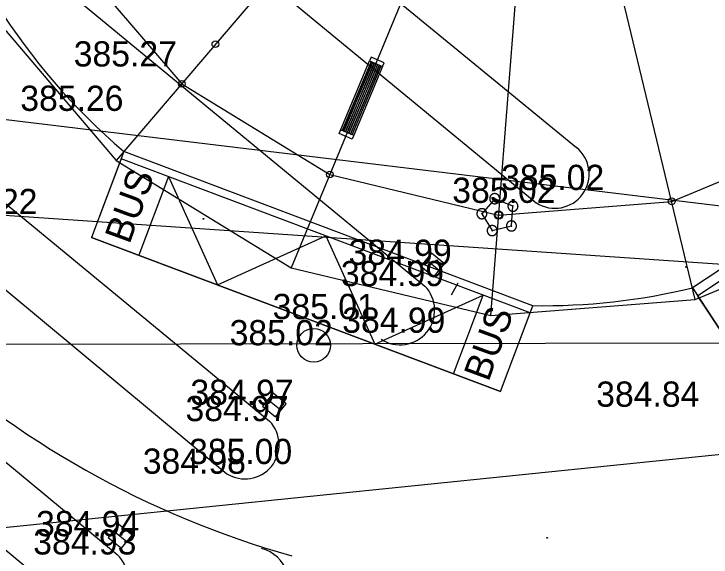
# Model space of a CAD drawing. Extents: x -438233 to -437334, y -1133133 to -1132623.
# Drawn here: x -438073.66 to -438052.93, y -1132978.53 to -1132962.38 of the extents above; entities that cross this region are included whole.
import ezdxf

# ---------------------------------------------------------------- set-up
doc = ezdxf.new("R2010")
doc.units = 0
for name, color, linetype in [('MOBILIÁŘ', 7, 'Continuous'), ('OSY', 7, 'Continuous'), ('SILNA 1', 7, 'Continuous'), ('SILNA 2', 7, 'Continuous'), ('TENKA', 7, 'Continuous'), ('urban islands', 7, 'Continuous'), ('Vrstva 1', 7, 'Continuous'), ('Vrstva 10', 7, 'Continuous'), ('Vrstva 27', 7, 'Continuous'), ('Vrstva 3', 7, 'Continuous'), ('Vrstva 40', 7, 'Continuous')]:
    doc.layers.add(name, color=color, linetype=linetype)

# ---------------------------------------------------------------- blocks, each defined once
blk = doc.blocks.new('A$C32EE4163')
at = {"layer": 'SILNA 1'}
for radius in [1.25, 1.25, 1.13, 1.13]:
    blk.add_circle((0, 0), radius, dxfattribs=at)
blk = doc.blocks.new('A$C1C6D51B8')
at = {"layer": 'urban islands'}
for p, q in [((-23400, 4190), (-1200, 4190)), ((-1200, 3710), (-23400, 3710)), ((-23400, 3660), (-1200, 3660)), ((-23400, 3239), (-23400, 3300)), ((-23400, 3180), (-1200, 3180)), ((-22900, 3710), (-22900, 3660)), ((-22900, 3180), (-22900, 3130)), ((-22900, 2650), (-22900, 2600)), ((-22900, 2120), (-22900, 2070)), ((-22290, 3660), (-22290, 3710)), ((-22290, 3130), (-22290, 3180)), ((-21900, 3180), (-21900, 3130)), ((-21900, 2650), (-21900, 2600)), ((-21900, 2120), (-21900, 2070)), ((-19450, 3710), (-19450, 3660)), ((-19450, 3180), (-19450, 3130)), ((-19450, 2650), (-19450, 2600)), ((-19450, 2120), (-19450, 2070)), ((-18950, 3660), (-18950, 3710)), ((-18950, 3180), (-18950, 3130)), ((-18950, 2650), (-18950, 2600)), ((-18950, 2120), (-18950, 2070)), ((-14850, 3710), (-14850, 3660)), ((-14850, 3180), (-14850, 3130)), ((-14850, 2650), (-14850, 2600)), ((-14850, 2120), (-14850, 2070)), ((-14350, 3660), (-14350, 3710)), ((-14350, 3180), (-14350, 3130)), ((-14350, 2650), (-14350, 2600)), ((-14350, 2120), (-14350, 2070)), ((-10250, 3710), (-10250, 3660)), ((-10250, 3180), (-10250, 3130)), ((-10250, 2650), (-10250, 2600)), ((-10250, 2120), (-10250, 2070)), ((-9750, 3660), (-9750, 3710)), ((-9750, 3180), (-9750, 3130)), ((-9750, 2650), (-9750, 2600)), ((-9750, 2120), (-9750, 2070)), ((-5650, 3710), (-5650, 3660)), ((-5650, 3180), (-5650, 3130)), ((-5650, 2650), (-5650, 2600)), ((-5650, 2120), (-5650, 2070)), ((-5150, 3660), (-5150, 3710)), ((-5150, 3180), (-5150, 3130)), ((-5150, 2650), (-5150, 2600)), ((-5150, 2120), (-5150, 2070)), ((-2700, 3130), (-2700, 3180)), ((-2700, 2600), (-2700, 2650)), ((-2700, 2070), (-2700, 2120)), ((-2310, 3710), (-2310, 3660)), ((-2310, 3180), (-2310, 3130)), ((-2300, 3710), (-2300, 3660)), ((-1700, 3710), (-1700, 3660)), ((-1700, 3180), (-1700, 3130)), ((-1700, 2650), (-1700, 2600)), ((-1700, 2120), (-1700, 2070)), ((-1200, 3214), (-1200, 3200)), ((-23400, 976), (-23400, 978)), ((-23400, 815), (-23400, 911)), ((-23400, 530), (-1200, 530)), ((-23400, 480), (-1200, 480)), ((-22900, 1590), (-22900, 1540)), ((-22900, 1060), (-22900, 1010)), ((-22900, 480), (-22900, 530)), ((-22290, 1010), (-22290, 1060)), ((-22290, 530), (-22290, 480)), ((-21900, 1590), (-21900, 1540)), ((-21900, 1060), (-21900, 1010)), ((-19450, 1590), (-19450, 1540)), ((-19450, 1060), (-19450, 1010)), ((-19450, 530), (-19450, 480)), ((-18950, 1590), (-18950, 1540)), ((-18950, 1060), (-18950, 1010)), ((-18950, 480), (-18950, 530)), ((-14850, 1590), (-14850, 1540)), ((-14850, 1060), (-14850, 1010)), ((-14850, 530), (-14850, 480)), ((-14350, 1590), (-14350, 1540)), ((-14350, 1060), (-14350, 1010)), ((-14350, 480), (-14350, 530)), ((-10250, 1590), (-10250, 1540)), ((-10250, 1060), (-10250, 1010)), ((-10250, 530), (-10250, 480)), ((-9750, 1590), (-9750, 1540)), ((-9750, 1060), (-9750, 1010)), ((-9750, 480), (-9750, 530)), ((-5650, 1590), (-5650, 1540)), ((-5650, 1060), (-5650, 1010)), ((-5650, 530), (-5650, 480)), ((-5150, 1590), (-5150, 1540)), ((-5150, 1060), (-5150, 1010)), ((-5150, 480), (-5150, 530)), ((-2700, 1540), (-2700, 1590)), ((-2700, 1010), (-2700, 1060)), ((-2310, 1060), (-2310, 1010)), ((-2310, 480), (-2310, 530)), ((-2300, 530), (-2300, 480)), ((-1700, 1590), (-1700, 1540)), ((-1700, 1060), (-1700, 1010)), ((-1700, 530), (-1700, 480)), ((-1200, 890), (-1200, 951))]:
    blk.add_line(p, q, dxfattribs=at)
for points in [[(-1200, 0), (-1200, 4190), (0, 4190), (0, 0), (-23400, 0), (-23400, 4190), (-24600, 4190), (-24600, 0), (-23400, 0)], [(-23400, 3130), (-1200, 3130), (-1200, 2650), (-23400, 2650)], [(-2505, 3165), (-2531, 3180)], [(-2479, 3180), (-2505, 3165)], [(-1200, 3375), (-1200, 3279), (-1200, 3440)], [(-1200, 3241), (-1200, 3180), (-1200, 3241)], [(-1200, 1060), (-23400, 1060), (-23400, 1540), (-1200, 1540)], [(-23400, 949), (-23400, 1010), (-1200, 1010)], [(-2531, 1010), (-2505, 1025)], [(-2505, 1025), (-2479, 1010)]]:
    blk.add_lwpolyline(points, dxfattribs=at)
for points in [[(-1200, 2120), (-23400, 2120), (-23400, 2600), (-1200, 2600)], [(-23400, 2070), (-1200, 2070), (-1200, 1590), (-23400, 1590)]]:
    blk.add_lwpolyline(points, close=True, dxfattribs=at)
for centre, radius, start, end in [((-2505, 3240), 80, 228.59038, 311.40962), ((-2505, 3243), 67.7, 247.84515, 292.15485), ((-2505, 950), 80, 48.59038, 131.40962), ((-2505, 947), 67.7, 67.84515, 112.15485)]:
    blk.add_arc(centre, radius, start, end, dxfattribs=at)
blk = doc.blocks.new('A$C7A6F5A01')
at = {"layer": 'Vrstva 1'}
for p, q in [((-20, 32), (-39, 0)), ((-39, 0), (-20, -35)), ((18, 32), (-20, 32)), ((40, 0), (18, 32)), ((18, -35), (40, 0)), ((-20, -35), (18, -35))]:
    blk.add_line(p, q, dxfattribs=at)
for points in [[(1497, 0), (1491, 133), (1481, 203), (1479, 219), (1476, 236), (1474, 253), (1471, 269), (1468, 286), (1465, 302), (1461, 319), (1458, 335), (1454, 351), (1450, 367), (1446, 383), (1442, 399), (1437, 415), (1432, 431), (1428, 447), (1423, 463), (1418, 478), (1412, 494), (1407, 509), (1401, 524), (1396, 540), (1390, 555), (1383, 570), (1377, 585), (1371, 600), (1364, 615), (1358, 630), (1351, 644), (1344, 659), (1336, 673), (1329, 688), (1322, 702), (1314, 716), (1306, 730), (1298, 744), (1290, 758), (1282, 772), (1274, 786), (1265, 799), (1256, 813), (1248, 826), (1239, 840), (1229, 853), (1220, 866), (1211, 879), (1201, 892), (1192, 905), (1182, 917), (1172, 930), (1162, 942), (1152, 955), (1142, 967), (1131, 979), (1121, 991), (1110, 1003), (1099, 1015), (1088, 1026), (1077, 1038), (1066, 1049), (1055, 1061), (1044, 1072), (1032, 1083), (1020, 1094), (1009, 1105), (997, 1115), (985, 1126), (973, 1136), (961, 1147), (948, 1157), (936, 1167), (923, 1177), (911, 1186), (898, 1196), (885, 1206), (872, 1215), (859, 1224), (846, 1233), (833, 1242), (819, 1251), (806, 1260), (792, 1268), (779, 1277), (765, 1285), (751, 1293), (737, 1301), (723, 1309), (709, 1317), (695, 1324), (681, 1332), (666, 1339), (652, 1346), (637, 1353), (623, 1360), (608, 1366), (593, 1373), (578, 1379), (563, 1385), (548, 1391), (533, 1397), (518, 1403), (503, 1409), (487, 1414), (472, 1419), (456, 1424), (441, 1429), (425, 1434), (409, 1438), (394, 1443), (378, 1447), (362, 1451), (346, 1455), (330, 1459), (314, 1462), (298, 1466), (281, 1469), (265, 1472), (249, 1475), (232, 1478), (216, 1480), (200, 1482), (183, 1485), (166, 1487), (150, 1488), (133, 1490), (116, 1491), (99, 1493), (83, 1494), (66, 1495), (-67, 1495), (-85, 1494), (-102, 1493), (-120, 1491), (-137, 1490), (-154, 1488), (-172, 1486), (-189, 1484), (-206, 1482), (-223, 1479), (-240, 1477), (-257, 1474), (-274, 1471), (-290, 1467), (-307, 1464), (-324, 1460), (-341, 1457), (-357, 1453), (-374, 1448), (-390, 1444), (-406, 1440), (-422, 1435), (-439, 1430), (-455, 1425), (-471, 1420), (-487, 1414), (-503, 1409), (-518, 1403), (-534, 1397), (-550, 1391), (-565, 1385), (-581, 1378), (-596, 1372), (-611, 1365), (-626, 1358), (-642, 1351), (-657, 1344), (-671, 1336), (-686, 1329), (-701, 1321), (-716, 1313), (-730, 1305), (-744, 1297), (-759, 1289), (-773, 1280), (-787, 1272), (-801, 1263), (-815, 1254), (-829, 1245), (-843, 1236), (-856, 1226), (-870, 1217), (-883, 1207), (-896, 1197), (-909, 1187), (-922, 1177), (-935, 1167), (-948, 1156), (-961, 1146), (-973, 1135), (-986, 1124), (-998, 1114), (-1010, 1102), (-1023, 1091), (-1035, 1080), (-1046, 1069), (-1058, 1057), (-1070, 1045), (-1081, 1033), (-1092, 1021), (-1104, 1009), (-1115, 997), (-1126, 985), (-1136, 972), (-1147, 960), (-1158, 947), (-1168, 934), (-1178, 921), (-1188, 908), (-1198, 895), (-1208, 882), (-1218, 869), (-1227, 855), (-1237, 841), (-1246, 828), (-1255, 814), (-1264, 800), (-1273, 786), (-1281, 772), (-1290, 758), (-1298, 743), (-1306, 729), (-1314, 714), (-1322, 700), (-1330, 685), (-1338, 670), (-1345, 655), (-1352, 640), (-1359, 625), (-1366, 610), (-1373, 594), (-1379, 579), (-1386, 564), (-1392, 548), (-1398, 532), (-1404, 517), (-1410, 501), (-1415, 485), (-1420, 469), (-1426, 453), (-1431, 437), (-1435, 420), (-1440, 404), (-1445, 388), (-1449, 371), (-1453, 355), (-1457, 338), (-1461, 321), (-1464, 304), (-1467, 288), (-1471, 271), (-1474, 254), (-1476, 237), (-1479, 220), (-1481, 202), (-1484, 185), (-1486, 168), (-1487, 150), (-1489, 133), (-1495, 67), (-1495, -66), (-1489, -136), (-1488, -153), (-1486, -170), (-1484, -186), (-1482, -203), (-1479, -220), (-1477, -236), (-1474, -253), (-1472, -269), (-1469, -285), (-1465, -302), (-1462, -318), (-1458, -334), (-1455, -350), (-1451, -366), (-1447, -382), (-1442, -398), (-1438, -414), (-1433, -429), (-1429, -445), (-1424, -461), (-1419, -476), (-1413, -492), (-1408, -507), (-1402, -522), (-1397, -537), (-1391, -552), (-1385, -568), (-1378, -582), (-1372, -597), (-1366, -612), (-1359, -627), (-1352, -641), (-1345, -656), (-1338, -670), (-1330, -685), (-1323, -699), (-1315, -713), (-1308, -727), (-1300, -741), (-1292, -755), (-1283, -769), (-1275, -783), (-1267, -796), (-1258, -810), (-1249, -823), (-1240, -837), (-1231, -850), (-1222, -863), (-1213, -876), (-1203, -889), (-1193, -902), (-1184, -914), (-1174, -927), (-1164, -939), (-1154, -952), (-1143, -964), (-1133, -976), (-1122, -988), (-1112, -1000), (-1101, -1012), (-1090, -1024), (-1079, -1035), (-1068, -1047), (-1057, -1058), (-1045, -1069), (-1034, -1080), (-1022, -1091), (-1010, -1102), (-999, -1113), (-987, -1124), (-974, -1134), (-962, -1145), (-950, -1155), (-938, -1165), (-925, -1175), (-912, -1185), (-900, -1194), (-887, -1204), (-874, -1213), (-861, -1223), (-848, -1232), (-834, -1241), (-821, -1250), (-808, -1259), (-794, -1267), (-780, -1276), (-767, -1284), (-753, -1292), (-739, -1300), (-725, -1308), (-711, -1316), (-696, -1324), (-682, -1331), (-668, -1338), (-653, -1346), (-639, -1353), (-624, -1360), (-609, -1366), (-595, -1373), (-580, -1379), (-565, -1385), (-550, -1392), (-534, -1397), (-519, -1403), (-504, -1409), (-489, -1414), (-473, -1420), (-458, -1425), (-442, -1430), (-426, -1434), (-411, -1439), (-395, -1444), (-379, -1448), (-363, -1452), (-347, -1456), (-331, -1460), (-315, -1463), (-299, -1467), (-283, -1470), (-266, -1473), (-250, -1476), (-233, -1479), (-217, -1481), (-200, -1484), (-184, -1486), (-167, -1488), (-151, -1490), (-134, -1491), (-67, -1495), (-1, -1495), (17, -1495), (34, -1494), (51, -1494), (68, -1494), (85, -1493), (103, -1492), (120, -1491), (137, -1489), (154, -1488), (171, -1486), (188, -1484), (204, -1482), (221, -1480), (238, -1477), (255, -1474), (271, -1471), (288, -1468), (305, -1465), (321, -1461), (338, -1458), (354, -1454), (370, -1450), (387, -1446), (403, -1441), (419, -1436), (435, -1432), (451, -1427), (467, -1422), (483, -1416), (498, -1411), (514, -1405), (530, -1399), (545, -1393), (561, -1387), (576, -1381), (592, -1374), (607, -1367), (622, -1361), (637, -1354), (652, -1346), (667, -1339), (682, -1331), (697, -1324), (711, -1316), (726, -1308), (740, -1300), (755, -1291), (769, -1283), (783, -1274), (797, -1265), (811, -1257), (825, -1247), (839, -1238), (852, -1229), (866, -1219), (879, -1210), (893, -1200), (906, -1190), (919, -1180), (932, -1169), (945, -1159), (958, -1149), (970, -1138), (983, -1127), (995, -1116), (1008, -1105), (1020, -1094), (1032, -1082), (1044, -1071), (1056, -1059), (1067, -1048), (1079, -1036), (1090, -1024), (1102, -1012), (1113, -999), (1124, -987), (1135, -975), (1146, -962), (1156, -949), (1167, -936), (1177, -923), (1187, -910), (1197, -897), (1207, -884), (1217, -870), (1227, -857), (1236, -843), (1246, -830), (1255, -816), (1264, -802), (1273, -788), (1281, -773), (1290, -759), (1298, -745), (1307, -730), (1315, -716), (1323, -701), (1330, -686), (1338, -671), (1346, -656), (1353, -641), (1360, -626), (1367, -611), (1374, -595), (1380, -580), (1387, -564), (1393, -549), (1399, -533), (1405, -517), (1410, -501), (1416, -486), (1421, -469), (1427, -453), (1431, -437), (1436, -421), (1441, -405), (1445, -388), (1450, -372), (1454, -355), (1457, -338), (1461, -322), (1465, -305), (1468, -288), (1471, -271), (1474, -254), (1476, -237), (1479, -220), (1481, -203), (1491, -136), (1494, -66)], [(-1, -101), (18, -98), (37, -92), (39, -91), (41, -90), (43, -89), (45, -88), (47, -87), (49, -86), (51, -85), (53, -84), (55, -83), (57, -82), (58, -81), (60, -80), (62, -78), (63, -77), (65, -76), (67, -75), (68, -73), (70, -72), (71, -70), (73, -69), (74, -68), (75, -66), (77, -65), (78, -63), (79, -62), (80, -60), (82, -59), (83, -57), (84, -55), (85, -54), (86, -52), (87, -50), (88, -49), (89, -47), (90, -45), (90, -44), (91, -42), (92, -40), (93, -38), (94, -37), (94, -35), (95, -33), (95, -31), (96, -29), (97, -28), (97, -26), (98, -24), (98, -22), (98, -20), (99, -18), (99, -16), (99, -15), (100, -13), (100, -11), (100, -9), (100, -7), (100, -5), (100, -3), (100, -1), (100, 1), (100, 2), (100, 4), (100, 6), (100, 8), (100, 10), (100, 12), (99, 14), (99, 16), (99, 18), (98, 19), (98, 21), (98, 23), (97, 25), (97, 27), (96, 29), (95, 31), (95, 32), (94, 34), (94, 36), (93, 38), (92, 40), (91, 41), (91, 43), (90, 45), (89, 47), (88, 48), (87, 50), (86, 52), (85, 53), (84, 55), (83, 57), (82, 58), (81, 60), (79, 61), (78, 63), (77, 64), (76, 66), (74, 67), (73, 69), (71, 70), (70, 72), (69, 73), (67, 74), (66, 76), (64, 77), (62, 78), (61, 79), (59, 81), (57, 82), (56, 83), (54, 84), (52, 85), (50, 86), (48, 87), (46, 88), (44, 89), (42, 90), (40, 91), (38, 92), (36, 93), (34, 94), (32, 94), (30, 95), (27, 96), (25, 96), (23, 97), (21, 98), (18, 98), (-17, 98), (-19, 98), (-21, 97), (-23, 96), (-26, 96), (-28, 95), (-30, 94), (-32, 94), (-34, 93), (-36, 92), (-38, 91), (-40, 90), (-42, 89), (-44, 88), (-46, 87), (-48, 86), (-50, 85), (-52, 84), (-54, 83), (-55, 82), (-57, 81), (-59, 80), (-60, 78), (-62, 77), (-64, 76), (-65, 75), (-67, 73), (-68, 72), (-70, 71), (-71, 69), (-72, 68), (-74, 66), (-75, 65), (-76, 63), (-78, 62), (-79, 60), (-80, 59), (-81, 57), (-82, 56), (-83, 54), (-85, 52), (-86, 51), (-87, 49), (-87, 47), (-88, 46), (-89, 44), (-90, 42), (-91, 41), (-92, 39), (-92, 37), (-93, 35), (-94, 34), (-94, 32), (-95, 30), (-96, 28), (-96, 26), (-97, 25), (-97, 23), (-98, 21), (-98, 19), (-98, 17), (-99, 15), (-99, 13), (-99, 12), (-99, 10), (-100, 8), (-100, 6), (-100, 4), (-100, 2), (-100, 0), (-100, -2), (-100, -3), (-100, -5), (-100, -7), (-100, -9), (-99, -11), (-99, -13), (-99, -15), (-99, -17), (-98, -18), (-98, -20), (-98, -22), (-97, -24), (-97, -26), (-96, -28), (-96, -29), (-95, -31), (-94, -33), (-94, -35), (-93, -37), (-92, -38), (-92, -40), (-91, -42), (-90, -44), (-89, -45), (-88, -47), (-87, -49), (-86, -50), (-85, -52), (-84, -54), (-83, -55), (-82, -57), (-80, -58), (-79, -60), (-78, -62), (-77, -63), (-75, -65), (-74, -66), (-72, -68), (-71, -69), (-70, -71), (-68, -72), (-66, -73), (-65, -75), (-63, -76), (-61, -77), (-60, -79), (-58, -80), (-56, -81), (-54, -82), (-52, -83), (-50, -85), (-48, -86), (-46, -87), (-44, -88), (-42, -89), (-40, -90), (-38, -91), (-36, -92), (-17, -98)]]:
    blk.add_lwpolyline(points, close=True, dxfattribs=at)
blk = doc.blocks.new('A$C5CBC2F6B')
at = {"layer": 'DEFPOINTS'}
blk.add_lwpolyline([(0, 5), (-4.76, 1.55), (-2.94, -4.05), (2.94, -4.05), (4.76, 1.55)], close=True, dxfattribs=at)
at = {"layer": 'MOBILIÁŘ', "xscale": 0.001, "yscale": 0.001}
for p in [(0, 5), (-4.75, 1.55), (4.76, 1.55), (-2.94, -4.05), (2.94, -4.05)]:
    blk.add_blockref('A$C7A6F5A01', p, dxfattribs=at)

msp = doc.modelspace()

# ---------------------------------------------------------------- linework, layer by layer
at = {"layer": 'OSY'}
for p, q in [((-438064.453, -1132959.52), (-438070.62, -1132966.746)), ((-438064.453, -1132959.52), (-438070.62, -1132966.746)), ((-438061.785, -1132961.153), (-438065.417, -1132969.932)), ((-438053.402, -1132970.872), (-438055.623, -1132961.636)), ((-438059.484, -1132971.354), (-438058.742, -1132961.883)), ((-438059.484, -1132971.354), (-438058.742, -1132961.883))]:
    msp.add_line(p, q, dxfattribs=at)
for points in [[(-438050.507, -1132933.894), (-438056.44, -1132932.473), (-438062.522, -1132932.954), (-438068.157, -1132935.291), (-438072.795, -1132939.255), (-438075.98, -1132944.458), (-438077.402, -1132950.391), (-438076.921, -1132956.473), (-438074.584, -1132962.109), (-438070.62, -1132966.746), (-438065.417, -1132969.932), (-438059.484, -1132971.354), (-438053.402, -1132970.872), (-438047.766, -1132968.535), (-438043.129, -1132964.571), (-438039.943, -1132959.368), (-438038.521, -1132953.435), (-438039.002, -1132947.353), (-438041.339, -1132941.718), (-438045.304, -1132937.08)], [(-438056.674, -1132935.463), (-438061.82, -1132935.87), (-438066.589, -1132937.848), (-438070.513, -1132941.202), (-438073.208, -1132945.605), (-438074.411, -1132950.625), (-438074.004, -1132955.771), (-438072.027, -1132960.54), (-438068.673, -1132964.464), (-438064.27, -1132967.16), (-438059.25, -1132968.363), (-438054.103, -1132967.956), (-438049.335, -1132965.978), (-438045.411, -1132962.624), (-438042.715, -1132958.221), (-438041.512, -1132953.201), (-438041.919, -1132948.055), (-438043.897, -1132943.286), (-438047.251, -1132939.362), (-438051.654, -1132936.666)], [(-438056.674, -1132935.463), (-438061.82, -1132935.87), (-438066.589, -1132937.848), (-438070.513, -1132941.202), (-438073.208, -1132945.605), (-438074.411, -1132950.625), (-438074.004, -1132955.771), (-438072.027, -1132960.54), (-438068.673, -1132964.464), (-438064.27, -1132967.16), (-438059.25, -1132968.363), (-438054.103, -1132967.956), (-438049.335, -1132965.978), (-438045.411, -1132962.624), (-438042.715, -1132958.221), (-438041.512, -1132953.201), (-438041.919, -1132948.055), (-438043.897, -1132943.286), (-438047.251, -1132939.362), (-438051.654, -1132936.666)]]:
    msp.add_lwpolyline(points, close=True, dxfattribs=at)
at = {"layer": 'SILNA 1'}
for centre in [(-438067.672, -1132963.284), (-438068.673, -1132964.464), (-438068.673, -1132964.464), (-438064.27, -1132967.16), (-438064.27, -1132967.16), (-438054.104, -1132967.956), (-438054.104, -1132967.956), (-438059.25, -1132968.363), (-438059.25, -1132968.363)]:
    msp.add_circle(centre, 0.1, dxfattribs=at)
at = {"layer": 'SILNA 2'}
for points in [[(-438042.628, -1132963.381), (-438053.487, -1132970.529), (-438051.986, -1132972.809), (-438041.127, -1132965.661)], [(-438058.229, -1132971.058), (-438070.394, -1132966.474), (-438071.357, -1132969.028), (-438059.192, -1132973.612)]]:
    msp.add_lwpolyline(points, close=True, dxfattribs=at)
at = {"layer": 'Vrstva 1'}
for p, q in [((-438042.511, -1132963.579), (-438053.339, -1132970.773)), ((-438069.386, -1132963.947), (-438069.386, -1132963.947)), ((-438070.975, -1132965.267), (-438070.975, -1132965.267)), ((-438056.933, -1132966.353), (-438056.933, -1132966.353)), ((-438070.475, -1132966.689), (-438071.357, -1132969.028)), ((-438058.311, -1132971.273), (-438070.475, -1132966.689)), ((-438069.072, -1132967.218), (-438069.953, -1132969.557)), ((-438056.676, -1132967.619), (-438056.676, -1132967.619)), ((-438058.129, -1132968.002), (-438058.129, -1132968.002)), ((-438073.532, -1132968.336), (-438073.532, -1132968.336)), ((-438059.192, -1132973.612), (-438071.357, -1132969.028)), ((-438061.213, -1132969.844), (-438061.213, -1132969.844)), ((-438060.649, -1132970.734), (-438060.458, -1132970.381)), ((-438061.441, -1132970.477), (-438061.441, -1132970.477)), ((-438060.596, -1132973.083), (-438059.714, -1132970.744)), ((-438053.339, -1132970.773), (-438051.955, -1132972.856)), ((-438059.192, -1132973.612), (-438058.311, -1132971.273)), ((-438063.471, -1132971.457), (-438063.471, -1132971.457)), ((-438061.401, -1132971.863), (-438061.401, -1132971.863)), ((-438064.749, -1132972.235), (-438064.749, -1132972.235)), ((-438065.916, -1132974.007), (-438065.916, -1132974.007)), ((-438053.848, -1132974.062), (-438053.848, -1132974.062)), ((-438066.062, -1132974.491), (-438066.062, -1132974.491)), ((-438065.956, -1132975.766), (-438065.956, -1132975.766)), ((-438067.332, -1132976.054), (-438067.332, -1132976.054)), ((-438070.505, -1132977.911), (-438070.505, -1132977.911)), ((-438070.59, -1132978.455), (-438070.59, -1132978.455))]:
    msp.add_line(p, q, dxfattribs=at)
msp.add_lwpolyline([(-438069.072, -1132967.218), (-438067.614, -1132970.439), (-438064.393, -1132968.981), (-438062.935, -1132972.202), (-438059.714, -1132970.744)], dxfattribs=at)
for centre in [(-438068.03, -1132968.478), (-438053.669, -1132969.906), (-438057.808, -1132977.96), (-438057.808, -1132977.96)]:
    msp.add_circle(centre, 0.0127, dxfattribs=at)
for centre, radius, start, end in [((-438057.961, -1132951.909), 19.15, 161.159, 229.4804), ((-438057.962, -1132951.913), 27.6, 199.5386, 254.3601), ((-438057.961, -1132951.909), 19.15, 269.1887, 283.5125), ((-438066.6, -1132979.371), 1.136, 324.8416, 74.8044)]:
    msp.add_arc(centre, radius, start, end, dxfattribs=at)
at = {"layer": 'Vrstva 10'}
for points in [[(-438073.312, -1132952.929), (-438056.933, -1132966.353)], [(-438074.721, -1132954.349), (-438058.129, -1132968.002)], [(-438077.811, -1132956.991), (-438061.441, -1132970.477)], [(-438082.411, -1132961.014), (-438066.062, -1132974.491)], [(-438083.784, -1132962.385), (-438067.332, -1132976.054)], [(-438086.926, -1132964.916), (-438070.59, -1132978.455)], [(-438088.082, -1132966.508), (-438071.892, -1132980)]]:
    msp.add_lwpolyline(points, dxfattribs=at)
for centre, radius, start, end in [((-438057.578, -1132967.143), 1.02, 237.3387, 50.7554), ((-438062.183, -1132971.192), 1.031, 236.9675, 43.93), ((-438066.794, -1132975.194), 1.015, 237.9738, 43.8358), ((-438071.296, -1132979.182), 1.013, 233.9189, 45.8381)]:
    msp.add_arc(centre, radius, start, end, dxfattribs=at)
at = {"layer": 'Vrstva 27'}
for p, q in [((-438061.407, -1132969.686), (-438061.019, -1132970.002)), ((-438066.11, -1132973.849), (-438065.722, -1132974.165)), ((-438070.699, -1132977.753), (-438070.311, -1132978.069))]:
    msp.add_line(p, q, dxfattribs=at)
for points in [[(-438061.565, -1132969.879), (-438061.178, -1132970.196), (-438060.861, -1132969.809), (-438061.248, -1132969.492)], [(-438066.268, -1132974.042), (-438065.881, -1132974.359), (-438065.564, -1132973.972), (-438065.951, -1132973.655)], [(-438070.857, -1132977.946), (-438070.47, -1132978.263), (-438070.153, -1132977.876), (-438070.54, -1132977.559)]]:
    msp.add_lwpolyline(points, close=True, dxfattribs=at)
msp.add_circle((-438064.749, -1132972.235), 0.5, dxfattribs=at)
at = {"layer": 'Vrstva 40'}
for p in [(-438088.826, -1132972.232), (-438081.083, -1132978.377)]:
    msp.add_line(p, (-438019.505, -1132972.094), dxfattribs=at)
msp.add_lwpolyline([(-438099.752, -1132962.397), (-438019.505, -1132972.094), (-438094.126, -1132966.999)], dxfattribs=at)

# ---------------------------------------------------------------- block references
at = {"layer": 'MOBILIÁŘ'}
for name, p, xscale, yscale, rotation in [('A$C1C6D51B8', (-438063.993, -1132965.942), 0.0001, 9.999999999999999e-05, -112.71271423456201), ('A$C5CBC2F6B', (-438059.25, -1132968.363), 0.1, 0.10000000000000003, 13.523388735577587)]:
    msp.add_blockref(name, p, dxfattribs=dict(at, xscale=xscale, yscale=yscale, rotation=rotation))
at = {"layer": 'TENKA', "xscale": 0.1, "yscale": 0.10000000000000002}
msp.add_blockref('A$C32EE4163', (-438059.25, -1132968.363), dxfattribs=at)

# ---------------------------------------------------------------- texts
at = {"layer": 'Vrstva 1'}
for p in [(-438070.231, -1132969.253), (-438059.554, -1132973.343)]:
    msp.add_text('BUS', height=0.8, rotation=69.8585, dxfattribs=at).set_placement(p)
at = {"layer": 'Vrstva 3'}
for s, p in [('385.27 ', (-438071.886, -1132963.947)), ('385.26 ', (-438073.475, -1132965.267)), ('385.02 ', (-438059.176, -1132967.619)), ('385.02 ', (-438060.629, -1132968.002)), ('385.22 ', (-438076.032, -1132968.336)), ('384.99 ', (-438063.713, -1132969.844)), ('384.99 ', (-438063.941, -1132970.477)), ('385.01 ', (-438065.971, -1132971.457)), ('384.99 ', (-438063.901, -1132971.863)), ('385.02 ', (-438067.249, -1132972.235)), ('384.97 ', (-438068.416, -1132974.007)), ('384.84 ', (-438056.348, -1132974.062)), ('384.97 ', (-438068.562, -1132974.491)), ('385.00 ', (-438068.456, -1132975.766)), ('384.98 ', (-438069.832, -1132976.054)), ('384.94 ', (-438073.005, -1132977.911)), ('384.93 ', (-438073.09, -1132978.455))]:
    msp.add_text(s, height=0.75, dxfattribs=at).set_placement(p)

doc.saveas('drawing.dxf')
